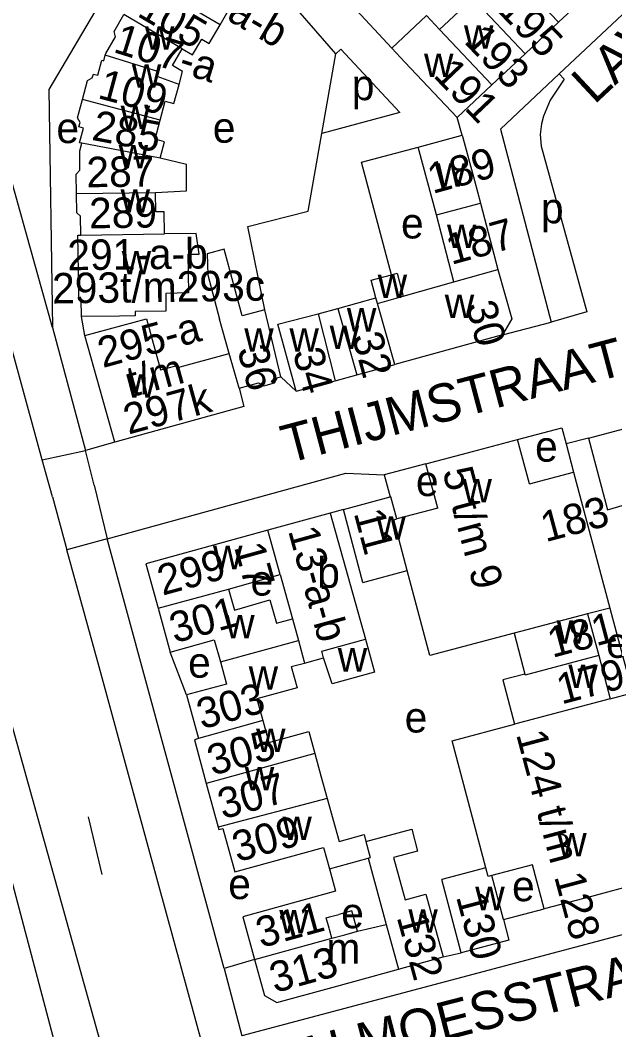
# Model space of a CAD drawing. Extents: x 161258 to 163262, y 380749 to 382054.
# Drawn here: x 162559.4 to 162637.4, y 381085.3 to 381217.9 of the extents above; entities that cross this region are included whole.
import ezdxf

# ---------------------------------------------------------------- set-up
doc = ezdxf.new("R2010")
doc.units = 0
for name, color, linetype in [('BLT_Basislijn', 7, 'Continuous'), ('BLT_Bebouwing', 7, 'Continuous'), ('BLT_Centroide', 7, 'Continuous'), ('BLT_Huisnummer', 7, 'Continuous'), ('BLT_Huisnummer_ tussenligend', 7, 'Continuous'), ('BLT_Huisnummer_reeks', 7, 'Continuous'), ('BLT_Onderverdeling_panden', 7, 'Continuous'), ('BLT_Straatnaam', 7, 'Continuous'), ('BLT_Vlakafsluiter', 7, 'Continuous')]:
    doc.layers.add(name, color=color, linetype=linetype)

msp = doc.modelspace()

# ---------------------------------------------------------------- linework, layer by layer
at = {"layer": 'BLT_Basislijn'}
for p, q in [((162579.58, 381236.67), (162563.16, 381208.76)), ((162600.84, 381213.45), (162590.6, 381225.25)), ((162563.66, 381177.51), (162551.97, 381219.27)), ((162608.17, 381214.2), (162602.97, 381219.79)), ((162598.99, 381203), (162600.84, 381213.45)), ((162609.22, 381205.74), (162598.99, 381203)), ((162622.45, 381203.58), (162629.08, 381178.21)), ((162567.89, 381176.45), (162567.46, 381178.95)), ((162622.7, 381176.54), (162629.08, 381178.21)), ((162563.66, 381177.51), (162568, 381161.35)), ((162624.65, 381162.81), (162630.48, 381164.34)), ((162630.48, 381164.34), (162631.05, 381162.22)), ((162571.83, 381162.45), (162568, 381161.35)), ((162633.98, 381163), (162631.05, 381162.22)), ((162631.05, 381162.22), (162632.03, 381158.53)), ((162569.11, 381156.81), (162568, 381161.35)), ((162612.65, 381159.61), (162607.19, 381158.15)), ((162607.19, 381158.15), (162607.96, 381155.26)), ((162563.63, 381155.3), (162565.54, 381148.32)), ((162601.82, 381153.62), (162600.08, 381153.13)), ((162586.18, 381093.35), (162570.84, 381149.78)), ((162553.65, 381141.92), (162570.6, 381081.13)), ((162636.79, 381140.68), (162639.75, 381129.54)), ((162548.79, 381140.57), (162564.46, 381081.62)), ((162581.22, 381129.26), (162579.11, 381134.89)), ((162568.35, 381113.28), (162570.12, 381105.67)), ((162622.83, 381099.76), (162628.18, 381101.19)), ((162590.17, 381094.51), (162586.18, 381093.35)), ((162614.92, 381094.87), (162617.29, 381095.42)), ((162586.18, 381093.35), (162588.5, 381084.5))]:
    msp.add_line(p, q, dxfattribs=at)
for points in [[(162630.15, 381210.83), (162648.15, 381227.77), (162646.78, 381229.23)], [(162609.22, 381205.74), (162601.48, 381214.05), (162600.84, 381213.45)], [(162562.3, 381160.15), (162549.17, 381208.07), (162548.73, 381210.51)], [(162622.45, 381203.58), (162630.15, 381210.83)], [(162630.15, 381210.83), (162630.81, 381210.13), (162628.96, 381207.35), (162628.06, 381205.28), (162627.8, 381204.24), (162627.66, 381202.87), (162627.75, 381201.31), (162633.75, 381179.59), (162629.08, 381178.21)], [(162563.16, 381208.76), (162563.66, 381177.51)], [(162591.5, 381179.84), (162589.27, 381190.76), (162597.18, 381192.77), (162598.99, 381203)], [(162608.14, 381184.43), (162604.18, 381199.21), (162611.62, 381201.21)], [(162593.59, 381171.04), (162595.6, 381169.14)], [(162633.98, 381163), (162638.75, 381164.26), (162641.23, 381154.97)], [(162633.98, 381163), (162636.48, 381153.57), (162641.23, 381154.97)], [(162570.84, 381149.78), (162602.15, 381158.39), (162607.19, 381158.15)], [(162583.37, 381083.14), (162577.61, 381104.26), (162574.28, 381116.4), (162569.76, 381132.95), (162565.54, 381148.32)], [(162650.43, 381100.95), (162588.5, 381084.5)]]:
    msp.add_lwpolyline(points, dxfattribs=at)
at = {"layer": 'BLT_Bebouwing'}
for p, q in [((162630.04, 381217.59), (162634.41, 381221.7)), ((162618.81, 381220.75), (162614.44, 381216.64)), ((162630.04, 381217.59), (162625.67, 381213.47)), ((162609.9, 381212.37), (162608.17, 381214.2)), ((162616.76, 381205.09), (162609.9, 381212.37)), ((162621.3, 381209.36), (162625.67, 381213.47)), ((162621.3, 381209.36), (162616.76, 381205.09)), ((162611.62, 381201.21), (162617.42, 381202.77)), ((162617.42, 381202.77), (162619.03, 381196.8)), ((162614.03, 381192.29), (162611.62, 381201.21)), ((162619.03, 381196.8), (162619.82, 381193.86)), ((162616.32, 381183.52), (162614.03, 381192.29)), ((162601.1, 381180.01), (162606.09, 381181.4)), ((162593.23, 381177.97), (162598.5, 381179.31)), ((162598.5, 381179.31), (162601.1, 381180.01)), ((162586.85, 381174.1), (162585.58, 381178.61)), ((162595.6, 381169.14), (162593.23, 381177.97)), ((162603.6, 381171.3), (162608.58, 381172.64)), ((162600.72, 381170.52), (162603.6, 381171.3)), ((162595.6, 381169.14), (162600.72, 381170.52)), ((162618.76, 381161.23), (162624.65, 381162.81)), ((162626.24, 381156.98), (162624.65, 381162.81)), ((162612.65, 381159.61), (162618.76, 381161.23)), ((162614.19, 381153.8), (162612.65, 381159.61)), ((162626.24, 381156.98), (162632.03, 381158.53)), ((162632.03, 381158.53), (162636.79, 381140.68)), ((162601.82, 381153.62), (162607.96, 381155.26)), ((162600.08, 381153.13), (162591.92, 381150.89)), ((162600.08, 381153.13), (162604.7, 381136.57)), ((162604.36, 381144.05), (162601.82, 381153.62)), ((162614.19, 381153.8), (162608.82, 381152.37)), ((162591.92, 381150.89), (162575.9, 381146.5)), ((162575.9, 381146.5), (162577.51, 381140.68)), ((162586.74, 381143.17), (162593.52, 381145.09)), ((162593.52, 381145.09), (162595.13, 381139.24)), ((162604.36, 381144.05), (162610.19, 381145.59)), ((162577.51, 381140.68), (162579.11, 381134.89)), ((162636.79, 381140.68), (162633.87, 381139.93)), ((162633.87, 381139.93), (162635.33, 381134.45)), ((162624.22, 381137.36), (162625.63, 381131.99)), ((162579.11, 381134.89), (162584.88, 381136.49)), ((162584.88, 381136.49), (162585.68, 381133.61)), ((162604.7, 381136.57), (162605.89, 381132.26)), ((162596.72, 381133.46), (162599.23, 381134.15)), ((162635.33, 381134.45), (162636.83, 381128.77)), ((162585.68, 381133.61), (162586.48, 381130.7)), ((162594.98, 381132.98), (162596.72, 381133.46)), ((162586.48, 381130.7), (162581.22, 381129.26)), ((162581.22, 381129.26), (162582.79, 381123.53)), ((162636.83, 381128.77), (162639.75, 381129.54)), ((162591.24, 381125.89), (162592.02, 381123.04)), ((162592.02, 381123.04), (162597.27, 381124.48)), ((162597.27, 381124.48), (162598.07, 381121.57)), ((162586.01, 381111.74), (162587.56, 381106.05)), ((162604.77, 381110.04), (162610.78, 381111.66)), ((162620.53, 381106.57), (162614.73, 381105.02)), ((162626.63, 381106.97), (162621.28, 381105.56)), ((162628.18, 381101.19), (162626.63, 381106.97)), ((162617.29, 381095.42), (162614.73, 381105.02)), ((162622.83, 381099.76), (162621.28, 381105.56)), ((162640.2, 381104.37), (162634.38, 381102.82)), ((162612.65, 381103.11), (162614.92, 381094.87)), ((162634.38, 381102.82), (162628.18, 381101.19)), ((162588.63, 381100.15), (162590.17, 381094.51)), ((162622.83, 381099.76), (162623.54, 381097.08)), ((162600.32, 381097.31), (162602, 381097.77)), ((162623.54, 381097.08), (162617.29, 381095.42)), ((162590.17, 381094.51), (162591.46, 381089.79)), ((162609.06, 381093.26), (162614.92, 381094.87)), ((162603.65, 381091.77), (162609.06, 381093.26))]:
    msp.add_line(p, q, dxfattribs=at)
for points in [[(162585.63, 381217.26), (162587.06, 381219.7), (162586.17, 381220.22), (162587.41, 381222.33)], [(162570.58, 381213.27), (162570.64, 381213.5), (162571.93, 381215.69), (162571.74, 381216.4), (162573.03, 381218.6)], [(162608.17, 381214.2), (162612.73, 381218.48), (162614.44, 381216.64)], [(162580.66, 381214.12), (162582.02, 381213.32), (162583.24, 381215.39), (162584.2, 381214.83), (162585.63, 381217.26)], [(162580.26, 381209.42), (162580.72, 381211.14), (162579.38, 381211.93), (162580.66, 381214.12)], [(162567.57, 381207.47), (162568.24, 381209.94), (162568.87, 381210.3), (162569.01, 381210.8), (162569.58, 381210.65), (162570.1, 381212.61), (162570.38, 381212.53)], [(162570.38, 381212.53), (162570.58, 381213.27)], [(162577.77, 381204.73), (162578.45, 381207.24), (162579.59, 381206.93), (162580.26, 381209.42)], [(162567.48, 381201.7), (162567.21, 381201.77), (162567.73, 381203.7), (162567.12, 381203.87), (162567.27, 381204.44), (162566.92, 381205.04), (162567.57, 381207.47)], [(162577.76, 381199.74), (162578.34, 381201.9), (162577.1, 381202.23), (162577.77, 381204.73)], [(162566.81, 381195.12), (162566.77, 381197.67), (162567.25, 381198.16), (162567.22, 381200.7), (162567.48, 381201.7)], [(162577.17, 381195.26), (162581.21, 381195.47), (162581.22, 381198.94), (162577.76, 381199.74)], [(162567.36, 381189.65), (162567.32, 381192.12), (162566.84, 381192.59), (162566.81, 381195.12)], [(162578.36, 381189.8), (162578.32, 381192.7), (162577.21, 381192.69), (162577.17, 381195.26)], [(162619.82, 381193.86), (162622.1, 381185.15)], [(162581.4, 381187.13), (162582.88, 381187.15), (162582.48, 381189.86), (162578.36, 381189.8)], [(162567.04, 381184.8), (162566.97, 381189.64), (162567.36, 381189.65)], [(162581.4, 381187.13), (162581.51, 381182.08), (162578.5, 381181.98), (162578.5, 381179.65), (162574.51, 381179.6), (162574.51, 381179.05), (162572.46, 381179.02), (162567.46, 381178.95)], [(162591.5, 381179.84), (162588.55, 381179.04), (162586.19, 381187.81), (162583.95, 381187.2), (162584.01, 381184.43), (162585.58, 381178.61)], [(162567.46, 381178.95), (162567.43, 381181.18), (162567.09, 381181.17), (162567.04, 381184.8)], [(162606.09, 381181.4), (162605.47, 381183.71), (162608.14, 381184.43)], [(162608.14, 381184.43), (162608.86, 381184.63), (162609.67, 381181.64)], [(162622.1, 381185.15), (162623.9, 381178.64), (162622.7, 381176.54)], [(162609.67, 381181.64), (162616.32, 381183.52)], [(162593.59, 381171.04), (162591.5, 381179.84)], [(162567.89, 381176.45), (162575.98, 381178.67), (162577.83, 381171.94), (162579.85, 381172.49), (162579.93, 381172.2), (162586.85, 381174.1)], [(162571.83, 381162.45), (162567.89, 381176.45)], [(162622.7, 381176.54), (162608.58, 381172.64)], [(162588.13, 381169.53), (162590.68, 381170.24), (162591.39, 381169.84), (162592.79, 381170.23), (162593.19, 381170.93), (162593.59, 381171.04)], [(162588.13, 381169.53), (162588.13, 381169.53), (162588.74, 381167.13), (162571.83, 381162.45), (162571.83, 381162.45)], [(162608.82, 381152.37), (162608.05, 381155.29), (162607.96, 381155.26)], [(162624.22, 381137.36), (162613.14, 381134.43), (162610.19, 381145.59)], [(162586.74, 381143.17), (162587.55, 381140.41), (162592.16, 381141.76), (162593.06, 381138.68), (162595.13, 381139.24)], [(162605.89, 381132.26), (162600.34, 381130.74), (162599.23, 381134.15)], [(162594.98, 381132.98), (162595.74, 381130.2), (162590.45, 381128.74), (162591.24, 381125.89)], [(162625.63, 381131.99), (162622.73, 381131.23), (162624.26, 381125.42)], [(162620.53, 381106.57), (162616.08, 381123.26), (162624.26, 381125.42)], [(162582.79, 381123.53), (162582.26, 381123.39), (162583.83, 381117.65)], [(162598.07, 381121.57), (162598.88, 381118.66), (162599.71, 381115.65)], [(162583.83, 381117.65), (162585.4, 381111.89)], [(162599.71, 381115.65), (162600.44, 381112.98), (162601.26, 381110.02), (162604.53, 381110.92), (162604.77, 381110.04)], [(162585.4, 381111.89), (162585.48, 381111.6), (162586.01, 381111.74)], [(162610.78, 381111.66), (162611.56, 381108.74), (162608.41, 381107.9), (162609.94, 381102.37), (162612.65, 381103.11)], [(162587.56, 381106.05), (162599.22, 381109.24), (162599.98, 381106.44)], [(162599.98, 381106.44), (162600.79, 381103.48)], [(162600.79, 381103.48), (162588.63, 381100.15)], [(162603.68, 381098.24), (162602.94, 381100.92), (162601.24, 381100.45)], [(162600.32, 381097.31), (162600, 381098.47), (162599.96, 381098.62), (162599.58, 381100), (162600, 381100.11), (162601.24, 381100.45)], [(162602, 381097.77), (162603.68, 381098.24)], [(162591.46, 381089.79), (162593.07, 381088.87), (162600, 381090.76), (162603.65, 381091.77)]]:
    msp.add_lwpolyline(points, dxfattribs=at)
at = {"layer": 'BLT_Onderverdeling_panden'}
for p, q in [((162623.18, 381224.87), (162630.04, 381217.59)), ((162585.63, 381217.26), (162576.15, 381222.83)), ((162625.67, 381213.47), (162618.81, 381220.75)), ((162580.66, 381214.12), (162573.03, 381218.6)), ((162614.44, 381216.64), (162621.3, 381209.36)), ((162577.77, 381204.73), (162567.57, 381207.47)), ((162577.76, 381199.74), (162567.48, 381201.7)), ((162566.81, 381195.12), (162577.17, 381195.26)), ((162614.03, 381192.29), (162619.82, 381193.86)), ((162567.36, 381189.65), (162578.36, 381189.8)), ((162606.29, 381180.68), (162609.67, 381181.64)), ((162598.5, 381179.31), (162600.72, 381170.52)), ((162601.1, 381180.01), (162603.6, 381171.3)), ((162588.13, 381169.53), (162586.85, 381174.1)), ((162577.51, 381140.68), (162586.74, 381143.17)), ((162633.87, 381139.93), (162624.22, 381137.36)), ((162595.13, 381139.24), (162595.91, 381136.42)), ((162585.68, 381133.61), (162595.91, 381136.42)), ((162595.91, 381136.42), (162596.68, 381133.61)), ((162598.99, 381135), (162604.7, 381136.57)), ((162599.23, 381134.15), (162598.99, 381135)), ((162596.68, 381133.61), (162596.72, 381133.46)), ((162636.83, 381128.77), (162624.26, 381125.42)), ((162591.24, 381125.89), (162582.79, 381123.53)), ((162598.07, 381121.57), (162583.83, 381117.65)), ((162599.71, 381115.65), (162585.4, 381111.89)), ((162604.77, 381110.04), (162605.35, 381107.92)), ((162605.05, 381107.84), (162607.44, 381099.14)), ((162603.68, 381098.24), (162607.44, 381099.14)), ((162607.44, 381099.14), (162609.06, 381093.26)), ((162590.17, 381094.51), (162600, 381097.22)), ((162600, 381097.22), (162600.32, 381097.31))]:
    msp.add_line(p, q, dxfattribs=at)
for points in [[(162580.26, 381209.42), (162577.4, 381210.48), (162577.59, 381211.07), (162570.58, 381213.27)], [(162616.32, 381183.52), (162622.1, 381185.15)], [(162606.29, 381180.68), (162606.09, 381181.4)], [(162608.58, 381172.64), (162606.29, 381180.68)], [(162610.19, 381145.59), (162608.42, 381152.27), (162608.82, 381152.37)], [(162593.52, 381145.09), (162591.92, 381150.89)], [(162635.33, 381134.45), (162625.66, 381131.88), (162625.63, 381131.99)], [(162599.98, 381106.44), (162605.05, 381107.84)], [(162605.05, 381107.84), (162605.35, 381107.92)], [(162621.28, 381105.56), (162620.83, 381105.44), (162620.53, 381106.57)]]:
    msp.add_lwpolyline(points, dxfattribs=at)
at = {"layer": 'BLT_Vlakafsluiter'}
for p, q in [((162617.42, 381202.77), (162616.76, 381205.09)), ((162562.3, 381160.15), (162568, 381161.35)), ((162563.63, 381155.3), (162562.3, 381160.15)), ((162569.11, 381156.81), (162570.84, 381149.78)), ((162570.84, 381149.78), (162565.54, 381148.32))]:
    msp.add_line(p, q, dxfattribs=at)

# ---------------------------------------------------------------- texts
at = {"layer": 'BLT_Centroide'}
for s, p in [('w', (162575.77, 381214)), ('w', (162617.64, 381214.11)), ('w', (162612.4, 381210.42)), ('w', (162574.06, 381209)), ('p', (162602.92, 381207.37)), ('w', (162572.59, 381203.59)), ('e', (162564.16, 381201.73)), ('e', (162584.68, 381201.78)), ('w', (162572.33, 381198.41)), ('w', (162614.02, 381196)), ('w', (162572.58, 381192.59)), ('p', (162627.74, 381191.2)), ('e', (162609.38, 381189.21)), ('w', (162615.41, 381187.96)), ('w', (162572.73, 381184.5)), ('w', (162606.32, 381181.39)), ('w', (162615.12, 381178.75)), ('w', (162602.28, 381176.99)), ('w', (162600.02, 381174.7)), ('w', (162588.81, 381174.34)), ('w', (162594.74, 381174.34)), ('w', (162573.33, 381168.3)), ('e', (162626.97, 381159.9)), ('e', (162611.34, 381155.38)), ('w', (162617.44, 381154.55)), ('w', (162606.14, 381149.67)), ('w', (162584.71, 381145.78)), ('b', (162598.38, 381143.36)), ('e', (162589.63, 381142.31)), ('w', (162586.31, 381136.71)), ('w', (162629.8, 381136)), ('e', (162636.28, 381134.13)), ('w', (162601.08, 381132.34)), ('e', (162581.44, 381131.53)), ('w', (162589.39, 381129.97)), ('w', (162631.34, 381130.19)), ('e', (162609.86, 381124.33)), ('w', (162590.36, 381121.78)), ('w', (162588.88, 381116.72)), ('w', (162593.81, 381110.22)), ('w', (162629.88, 381108.06)), ('e', (162586.71, 381102.46)), ('e', (162623.95, 381102.18)), ('w', (162619.12, 381101)), ('w', (162593.41, 381097.96)), ('e', (162601.54, 381098.63)), ('w', (162610.34, 381098.05)), ('m', (162599.59, 381094))]:
    msp.add_text(s, height=4, dxfattribs=at).set_placement(p)
at = {"layer": 'BLT_Huisnummer'}
for s, rotation, p in [('105', 329.5762, (162574.61, 381218.49)), ('195', 313.6052, (162621.89, 381219.12)), ('191', 313.6052, (162613.49, 381210.54)), ('109', 344.9847, (162569.44, 381207.67)), ('285', 349.237, (162568.67, 381202.17)), ('189', 15.4292, (162613.52, 381195.04)), ('289', 0.7916, (162568.47, 381190.53)), ('187', 15.4292, (162615.97, 381185.72)), ('30', 285.4292, (162617.84, 381180.44)), ('32', 285.4292, (162602.91, 381176.34)), ('36', 285.426, (162587.86, 381174.63)), ('34', 285.4292, (162595.14, 381174.27)), ('11', 284.8913, (162603.16, 381153.16)), ('301', 15.4021, (162579.66, 381136.04)), ('181', 14.8882, (162629.23, 381134.12)), ('179', 14.8882, (162630.43, 381128)), ('303', 15.3986, (162583.23, 381124.73)), ('309', 15.3973, (162587.89, 381107.29)), ('130', 284.8863, (162616.58, 381102.78)), ('311', 15.4004, (162591.01, 381096.02)), ('132', 285.3856, (162608.79, 381100.11)), ('313', 15.3984, (162592.8, 381090.11))]:
    msp.add_text(s, height=4, rotation=rotation, dxfattribs=at).set_placement(p)
at = {"layer": 'BLT_Huisnummer_ tussenligend'}
for s, rotation, p in [('193', 313.6052, (162617.53, 381215)), ('287', 0.7916, (162568.12, 381195.92)), ('305', 15.3986, (162584.62, 381118.65)), ('307', 15.3986, (162585.99, 381112.92))]:
    msp.add_text(s, height=4, rotation=rotation, dxfattribs=at).set_placement(p)
at = {"layer": 'BLT_Huisnummer_reeks'}
for s, rotation, p in [('103-a-b', 329.5664, (162577.13, 381223.45)), ('107-a', 342.6041, (162571.48, 381213.72)), ('291-a-b', 0.7916, (162565.62, 381185.02)), ('293t/m293c', 0.7906, (162563.62, 381180.66)), ('295-a', 15.4013, (162570.24, 381172.18)), ('t/m', 15.4013, (162574.05, 381168.36)), ('297k', 15.4013, (162573.61, 381163.44)), ('5 t/m 9', 284.9736, (162614.79, 381158.64)), ('183', 14.8882, (162628.34, 381149.31)), ('13-a-b', 285.3942, (162594.54, 381150.84)), ('17', 285.4733, (162587.45, 381148.71)), ('299', 15.4013, (162578.08, 381142.29)), ('124 t/m 128', 284.9736, (162624.46, 381124.1))]:
    msp.add_text(s, height=4, rotation=rotation, dxfattribs=at).set_placement(p)
at = {"layer": 'BLT_Straatnaam'}
for s, height, rotation, p in [('LAVENDELLAAN', 4.9999, 43.0476, (162634.73, 381206.7)), ('THIJMSTRAAT', 5, 14.8317, (162594.47, 381159.64)), ('KALMOESSTRAAT', 5, 14.4075, (162592.11, 381077.98))]:
    msp.add_text(s, height=height, rotation=rotation, dxfattribs=at).set_placement(p)

doc.saveas('drawing.dxf')
